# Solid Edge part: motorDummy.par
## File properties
Author: morva
Template: iso metric part.par
Last saved by: morva
Revision: 4
Application: Solid Edge
Density: 2023.87054599614 kg/m^3
Accuracy: 0.990
Username: morva
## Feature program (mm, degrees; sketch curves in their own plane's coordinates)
sketch for "unnamed RevolvedProtrusion 1" plane through (0, 0, 0) normal (0, 0, 1) x-axis (1, 0, 0)
  line (-80, 6) -> (-56, 6)
  line (-56, 6) -> (-56, 10)
  line (-56, 10) -> (-22.5, 10)
  line (-22.5, 10) -> (-22.5, 127)
  line (-22.5, 127) -> (22.5, 127)
  line (22.5, 127) -> (22.5, 10)
  line (22.5, 10) -> (56, 10)
  line (56, 10) -> (56, 6)
  line (56, 6) -> (80, 6)
  line (80, 6) -> (80, 0)
  line (-80, 0) -> (-80, 6)
  dimension (linear) = 80
  dimension (linear) = 22.5
revolve "unnamed RevolvedProtrusion 1" add finite 360 deg about sketch line (80, 0) -> (-80, 0)
fillet "unnamed Round 1"
sketch for "unnamed Cutout 1" #1 plane through (-80, 0, 0) normal (-1, 0, 0) x-axis (0, -1, 0)
  line (-3.3166, 5) -> (3.3166, 5)
sketch for "unnamed Cutout 1" #2 plane through (-80, 0, 0) normal (-1, 0, 0) x-axis (0, -1, 0)
  line (-3.3166, -5) -> (3.3166, -5)
  arc centre (0, 0) radius 6 from (-3.3166, -5) to (3.3166, -5) ccw
extrude "unnamed Cutout 1" cut to key point along -normal
sketch for "unnamed Cutout 2" #1 plane through (80, 0, 0) normal (1, 0, 0) x-axis (0, 1, 0)
  line (-3.3166, 5) -> (3.3166, 5)
sketch for "unnamed Cutout 2" #2 plane through (80, 0, 0) normal (1, 0, 0) x-axis (0, 1, 0)
  line (-3.3166, -5) -> (3.3166, -5)
  arc centre (0, 0) radius 6 from (3.3166, -5) to (-3.3166, -5) cw
extrude "unnamed Cutout 2" cut to key point along -normal
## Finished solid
Body 1: solid body, 19 faces, 32 edges, 16 vertices.
  Faces by surface: plane 10, cylinder 7, torus 2
  Edges by curve: circle 16, line 16
Bounding box of the edges (mm; curved faces can reach further): 160.000 x 254.000 x 254.000, from (-80, -127, -127) to (80, 127, 127).
Cylindrical faces by radius (mm): R6 x4, R10 x2, R127 x1
Toroidal faces (ring radius, tube radius in mm): R107 r20 x2
Planar faces by outward normal: +x 3, +z 2, -x 3, -z 2
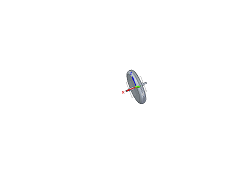
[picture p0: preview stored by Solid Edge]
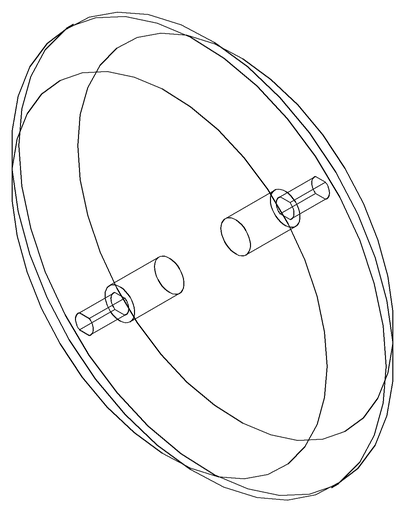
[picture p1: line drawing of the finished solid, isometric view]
